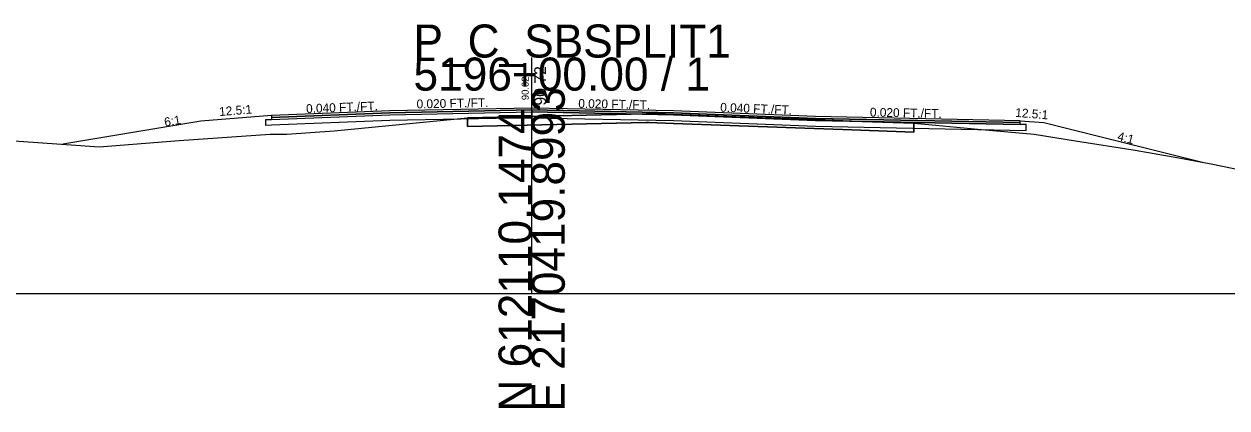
# Model space of a CAD drawing. Extents: x -26 to 1303, y -3010 to 12023.
# Drawn here: x 1107.1 to 1208.8, y -9.7 to 22.8 of the extents above; entities that cross this region are included whole.
import ezdxf

# ---------------------------------------------------------------- set-up
doc = ezdxf.new("R2010")
doc.units = 0
for name, color, linetype in [('RD_GPK_XS_Cell', 7, 'Continuous'), ('RD_XS_Base', 7, 'Continuous'), ('RD_XS_ExGround', 7, 'Continuous'), ('RD_XS_ExPaveRet', 7, 'Continuous'), ('RD_XS_Greenside', 7, 'Continuous'), ('RD_XS_Pave', 7, 'Continuous'), ('RD_XS_PaveOvlay_CP', 7, 'Continuous'), ('RD_XS_TieSlope', 7, 'Continuous'), ('RD_XS_TX_Elev_EX', 7, 'Continuous'), ('RD_XS_TX_Elev_PR', 7, 'Continuous'), ('RD_XS_TX_ShdSlope', 7, 'Continuous'), ('RD_XS_TX_Slope', 7, 'Continuous')]:
    doc.layers.add(name, color=color, linetype=linetype)

msp = doc.modelspace()

# ---------------------------------------------------------------- linework, layer by layer
at = {"layer": 'RD_GPK_XS_Cell'}
for p, q in [((1150, 0), (1150, 20)), ((1000, 0), (1150, 0)), ((1150, 0), (1300, 0))]:
    msp.add_line(p, q, dxfattribs=at)
at = {"layer": 'RD_XS_Base'}
for p, q in [((1138, 15.16), (1150, 15.4)), ((1150, 15.4), (1150, 15.56)), ((1150, 15.56), (1150, 14.9)), ((1150, 15.4), (1150, 15.4)), ((1162, 15.16), (1150, 15.4)), ((1150, 15.4), (1150, 15.4)), ((1150, 15.4), (1150, 14.9)), ((1127.5, 14.74), (1128, 14.76)), ((1127.5, 14.24), (1127.5, 14.74)), ((1127.5, 14.74), (1127.5, 14.74)), ((1128, 14.26), (1127.5, 14.24)), ((1128, 14.76), (1138, 15.16)), ((1128, 14.76), (1128, 14.76)), ((1138, 14.66), (1128, 14.26)), ((1128, 14.26), (1128, 14.26)), ((1136, 15.08), (1136, 15.08)), ((1136, 14.58), (1136, 14.58)), ((1150, 14.9), (1138, 14.66)), ((1150, 14.9), (1150, 14.9)), ((1150, 14.9), (1162, 14.66)), ((1150, 14.9), (1150, 14.9)), ((1174, 14.68), (1162, 15.16)), ((1162, 15.16), (1162, 15.16)), ((1162, 14.66), (1162, 14.66)), ((1162, 14.66), (1174, 14.18)), ((1191.32, 14.33), (1174, 14.68)), ((1174, 14.68), (1174, 14.68)), ((1191.82, 14.32), (1191.32, 14.33)), ((1191.32, 14.33), (1191.32, 14.33)), ((1191.82, 13.82), (1191.82, 14.32)), ((1191.82, 14.32), (1191.82, 14.32)), ((1127.5, 14.24), (1127.5, 14.24)), ((1127.5, 14.24), (1127.5, 14.24)), ((1174, 14.18), (1174, 14.18)), ((1174, 14.18), (1191.82, 13.82)), ((1191.82, 13.82), (1191.82, 13.82)), ((1191.82, 13.82), (1191.82, 13.82))]:
    msp.add_line(p, q, dxfattribs=at)
at = {"layer": 'RD_XS_ExGround'}
msp.add_lwpolyline([(1098.16, 13.51), (1111.84, 12.55), (1113.42, 12.44), (1120.18, 12.97), (1127.87, 13.5), (1129.29, 13.5), (1133.29, 13.8), (1144.57, 14.9), (1159.69, 15.24), (1159.95, 15.25), (1162, 15.17), (1177.08, 14.62), (1182.34, 14.43), (1184.2, 14.27), (1187.75, 13.93), (1192.5, 13.5), (1196.01, 12.94), (1201.05, 12.14), (1204.75, 11.51), (1207.62, 10.96), (1209.95, 10.5)], dxfattribs=at)
at = {"layer": 'RD_XS_ExPaveRet'}
for points in [[(1182.34, 14.43), (1182.34, 14.43), (1182.34, 13.68), (1182.34, 13.68), (1177.08, 13.87), (1177.08, 13.87), (1162, 14.42), (1162, 14.42), (1159.95, 14.5), (1159.69, 14.49), (1159.69, 14.49), (1144.57, 14.15), (1144.57, 14.15), (1144.57, 14.15), (1144.57, 14.9), (1144.57, 14.9), (1144.57, 14.9), (1144.57, 14.9), (1159.69, 15.24), (1159.69, 15.24), (1159.95, 15.25), (1162, 15.17), (1162, 15.17), (1177.08, 14.62), (1177.08, 14.62), (1182.34, 14.43), (1182.34, 14.43)], [(1182.34, 14.43), (1177.08, 14.62), (1162, 15.17), (1159.95, 15.25), (1159.69, 15.24), (1144.57, 14.9), (1144.57, 14.9), (1144.57, 14.15), (1144.57, 14.15), (1159.69, 14.49), (1159.95, 14.5), (1162, 14.42), (1177.08, 13.87), (1182.34, 13.68), (1182.34, 13.68), (1182.34, 14.43), (1182.34, 14.43)]]:
    msp.add_lwpolyline(points, dxfattribs=at)
at = {"layer": 'RD_XS_Greenside'}
for p, q in [((1122, 14.6), (1110.34, 12.65)), ((1193.32, 14.49), (1206.86, 11.1))]:
    msp.add_line(p, q, dxfattribs=at)
at = {"layer": 'RD_XS_Pave'}
for p, q in [((1138, 15.48), (1128, 15.08)), ((1138, 15.32), (1128, 14.92)), ((1128, 14.92), (1138, 15.32)), ((1136, 15.4), (1136, 15.4)), ((1150, 15.72), (1138, 15.48)), ((1150, 15.56), (1138, 15.32)), ((1138, 15.32), (1150, 15.56)), ((1138, 15.16), (1150, 15.4)), ((1162, 15.48), (1150, 15.72)), ((1150, 15.4), (1150, 15.56)), ((1150, 15.56), (1162, 15.32)), ((1162, 15.32), (1150, 15.56)), ((1150, 15.56), (1150, 15.56)), ((1150, 15.56), (1150, 15.4)), ((1150, 15.4), (1150, 15.4)), ((1150, 15.4), (1150, 15.4)), ((1150, 15.4), (1150, 15.4)), ((1150, 15.4), (1162, 15.16)), ((1174, 15), (1162, 15.48)), ((1162, 15.48), (1162, 15.48)), ((1162, 15.32), (1162, 15.32)), ((1162, 15.32), (1174, 14.84)), ((1174, 14.84), (1162, 15.32)), ((1162, 15.32), (1162, 15.32)), ((1128, 14.76), (1138, 15.16)), ((1128, 15.08), (1128, 15.08)), ((1128, 15.08), (1128, 14.92)), ((1128, 14.92), (1128, 14.92)), ((1128, 14.92), (1128, 14.76)), ((1128, 14.92), (1128, 14.92)), ((1128, 14.92), (1128, 14.92)), ((1128, 14.76), (1128, 14.76)), ((1128, 14.76), (1128, 14.76)), ((1136, 15.24), (1136, 15.24)), ((1136, 15.24), (1136, 15.24)), ((1136, 15.08), (1136, 15.08)), ((1162, 15.16), (1162, 15.16)), ((1162, 15.16), (1174, 14.68)), ((1191.32, 14.65), (1174, 15)), ((1174, 15), (1174, 15)), ((1174, 14.84), (1174, 14.84)), ((1174, 14.84), (1191.32, 14.49)), ((1191.32, 14.49), (1174, 14.84)), ((1174, 14.84), (1174, 14.84)), ((1174, 14.68), (1174, 14.68)), ((1174, 14.68), (1191.32, 14.33)), ((1191.32, 14.49), (1191.32, 14.65)), ((1191.32, 14.65), (1191.32, 14.65)), ((1191.32, 14.49), (1191.32, 14.49)), ((1191.32, 14.49), (1191.32, 14.49)), ((1191.32, 14.33), (1191.32, 14.49)), ((1191.32, 14.49), (1191.32, 14.49)), ((1191.32, 14.33), (1191.32, 14.33)), ((1191.32, 14.33), (1191.32, 14.33))]:
    msp.add_line(p, q, dxfattribs=at)
at = {"layer": 'RD_XS_PaveOvlay_CP'}
for p, q in [((1138, 15.48), (1128, 15.08)), ((1136, 15.4), (1136, 15.4)), ((1150, 15.72), (1138, 15.48)), ((1162, 15.48), (1150, 15.72)), ((1174, 15), (1162, 15.48)), ((1162, 15.48), (1162, 15.48)), ((1128, 15.08), (1128, 15.08)), ((1191.32, 14.65), (1174, 15)), ((1174, 15), (1174, 15)), ((1191.32, 14.65), (1191.32, 14.65))]:
    msp.add_line(p, q, dxfattribs=at)
at = {"layer": 'RD_XS_TieSlope'}
for p, q in [((1128, 15.08), (1122, 14.6)), ((1191.32, 14.65), (1193.32, 14.49))]:
    msp.add_line(p, q, dxfattribs=at)

# ---------------------------------------------------------------- texts
at = {"layer": 'RD_GPK_XS_Cell'}
for s, p in [('P_C_SBSPLIT1', (1140, 20)), ('5196+00.00 / 1', (1140, 17.2))]:
    msp.add_text(s, height=2.8, dxfattribs=at).set_placement(p)
for s, p in [('E 2170419.8993', (1152.8, -10)), ('N 612110.1474', (1150, -10))]:
    msp.add_text(s, height=2.8, rotation=90, dxfattribs=at).set_placement(p)
at = {"layer": 'RD_XS_TX_Elev_EX'}
msp.add_text('90.02', height=0.6, rotation=90, dxfattribs=at).set_placement((1149.75, 16.39))
at = {"layer": 'RD_XS_TX_Elev_PR'}
msp.add_text('90.72', height=1, rotation=90, dxfattribs=at).set_placement((1151.22, 15.93))
at = {"layer": 'RD_XS_TX_ShdSlope'}
for rotation, p in [(4.5739, (1123.59, 15.04)), (355.4261, (1190.89, 14.98))]:
    msp.add_text('12.5:1', height=0.75, rotation=rotation, dxfattribs=at).set_placement(p)
at = {"layer": 'RD_XS_TX_Slope'}
for s, rotation, p in [('0.020 FT./FT.', 1.1458, (1140.27, 15.69)), ('0.020 FT./FT.', 358.8542, (1153.94, 15.74)), ('0.040 FT./FT.', 2.2906, (1130.93, 15.29)), ('0.040 FT./FT.', 357.7094, (1165.94, 15.42)), ('0.020 FT./FT.', 358.8542, (1178.61, 15)), ('6:1', 9.4642, (1118.98, 14.15)), ('4:1', 345.9638, (1199.5, 13))]:
    msp.add_text(s, height=0.75, rotation=rotation, dxfattribs=at).set_placement(p)

doc.saveas('drawing.dxf')
